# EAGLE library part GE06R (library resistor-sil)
SIL RESISTOR
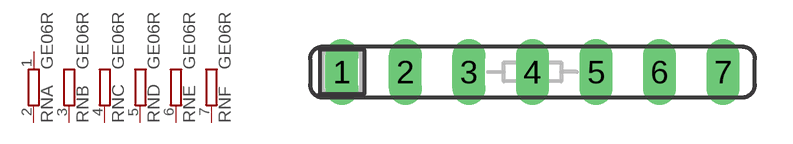
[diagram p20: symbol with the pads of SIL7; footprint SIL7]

Designator prefix RN; gates A=R-NV B=R-NV1 C=R-NV1 D=R-NV1 E=R-NV1 F=R-NV1

## GE06R (OC_FARNELL: unknown; OC_NEWARK: unknown)  [SIL7]
1  A:1  pas
2  A:2  pas
3  B:2  pas
4  C:2  pas
5  D:2  pas
6  E:2  pas
7  F:2  pas

## Footprint SIL7 (pad centres in mm)
Single In Line
drill 0.813 long: 1 -7.62,0; 2 -5.08,0; 3 -2.54,0; 4 0,0; 5 2.54,0; 6 5.08,0; 7 7.62,0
